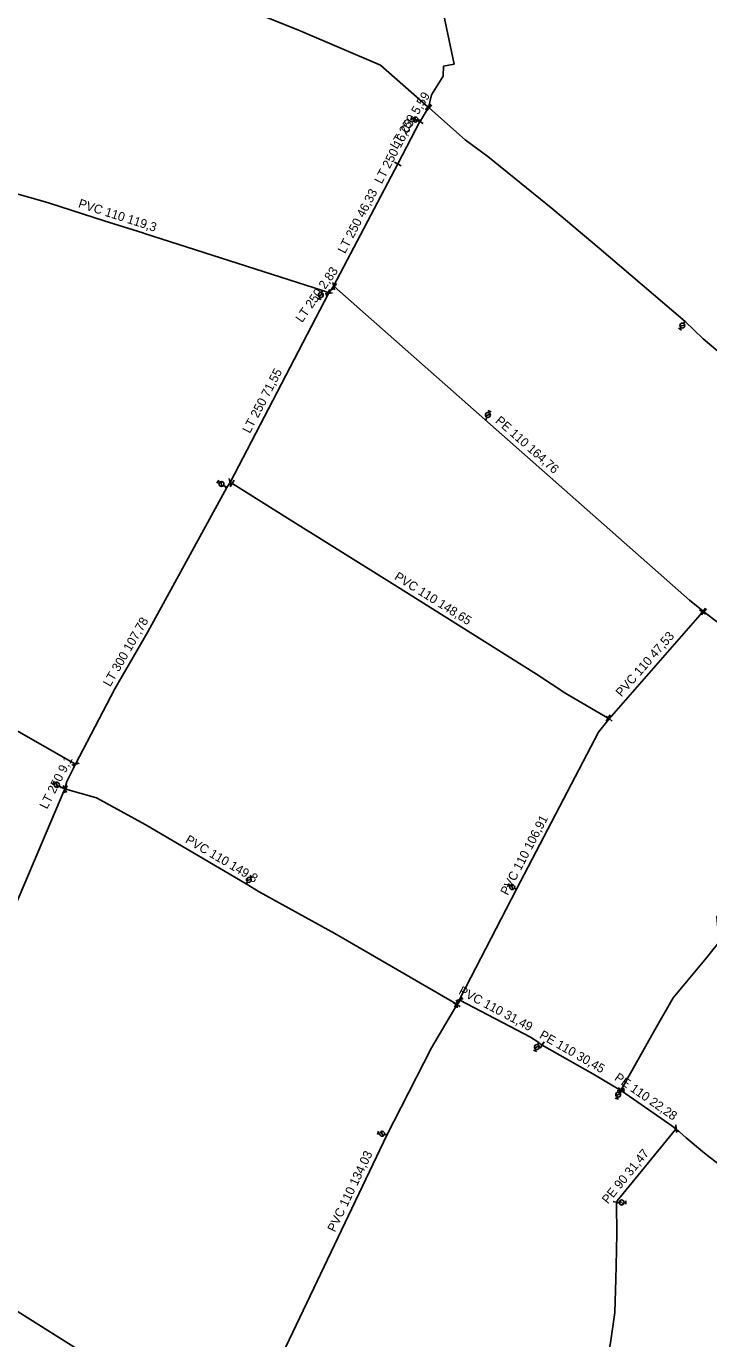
# Model space of a CAD drawing. Extents: x -736619 to -735426, y -1033122 to -1031044.
# Drawn here: x -736078.3 to -735849.4, y -1032731.9 to -1032291.7 of the extents above; entities that cross this region are included whole.
import ezdxf

# ---------------------------------------------------------------- set-up
doc = ezdxf.new("R2010")
doc.units = 0
for name, color, linetype in [('Vrstva 1', 7, 'Continuous'), ('Vrstva 17', 7, 'Continuous'), ('Vrstva 25', 7, 'Continuous'), ('Vrstva 29', 7, 'Continuous'), ('Vrstva 63', 7, 'Continuous')]:
    doc.layers.add(name, color=color, linetype=linetype)

# ---------------------------------------------------------------- blocks, each defined once
blk = doc.blocks.new('100')
at = {"layer": 'Vrstva 1'}
blk.add_circle((0, 0), 0.127, dxfattribs=at)
blk = doc.blocks.new('133')
at = {"layer": 'Vrstva 1'}
for p, q in [((0.28, 0), (0, 0)), ((0.54, 0.58), (1.7, -0.58)), ((1.94, 0), (2.52, 0)), ((2.52, 0.58), (2.52, -0.58))]:
    blk.add_line(p, q, dxfattribs=at)
blk.add_circle((1.105, 0.003), 0.825, dxfattribs=at)
blk = doc.blocks.new('147')
at = {"layer": 'Vrstva 1'}
blk.add_line((0, 1.27), (0, -1.27), dxfattribs=at)

msp = doc.modelspace()

# ---------------------------------------------------------------- linework, layer by layer
at = {"layer": 'Vrstva 17'}
for p, q in [((-735943.596, -1032318.709), (-735943.354, -1032318.926)), ((-735943.354, -1032318.926), (-735943.091, -1032319.148)), ((-735946.267, -1032323.694), (-735953.694, -1032337.895)), ((-735953.694, -1032337.895), (-735975.236, -1032378.911)), ((-735975.236, -1032378.911), (-735976.852, -1032381.236)), ((-735975.007, -1032379.034), (-735975.236, -1032378.911)), ((-735976.852, -1032381.236), (-735977.1, -1032381.05)), ((-736009.96, -1032444.666), (-736009.247, -1032445.08)), ((-735882.778, -1032523.942), (-735851.484, -1032488.165)), ((-735851.484, -1032488.165), (-735851.31, -1032487.854)), ((-735851.007, -1032488.105), (-735851.31, -1032487.854)), ((-735883.116, -1032523.716), (-735882.778, -1032523.942)), ((-736061.756, -1032539.17), (-736061.794, -1032539.148)), ((-736065.083, -1032547.585), (-736065.393, -1032547.472)), ((-735933.82, -1032619.656), (-735934.084, -1032619.516)), ((-735933.82, -1032619.656), (-735933.918, -1032619.842)), ((-735933.038, -1032618.179), (-735933.82, -1032619.656)), ((-735933.038, -1032618.179), (-735932.847, -1032618.28)), ((-735878.86, -1032648.571), (-735878.73, -1032648.384)), ((-735878.635, -1032648.727), (-735878.86, -1032648.571)), ((-735860.343, -1032661.446), (-735878.635, -1032648.727)), ((-735860.514, -1032661.65), (-735860.343, -1032661.446))]:
    msp.add_line(p, q, dxfattribs=at)
for points in [[(-735954.66, -1032212.952), (-735953.407, -1032215.657), (-735948.624, -1032232.346), (-735944.072, -1032253.819), (-735941.595, -1032272.005), (-735934.779, -1032304.372), (-735938.314, -1032305.089), (-735938.478, -1032308.409), (-735942.432, -1032314.719), (-735943.354, -1032318.926)], [(-736058.928, -1032278.254), (-736056.268, -1032278.805), (-736017.452, -1032285.347), (-735998.364, -1032288.387), (-735986.426, -1032293.223), (-735959.541, -1032304.754), (-735943.596, -1032318.709)], [(-735946.267, -1032323.694), (-735946.136, -1032323.443), (-735943.354, -1032318.926)], [(-735815.232, -1032429.97), (-735817.096, -1032425.726), (-735825.831, -1032417.995), (-735851.243, -1032396.548), (-735857.331, -1032390.732), (-735886.184, -1032366.165), (-735901.653, -1032353.103), (-735923.508, -1032335.433), (-735931.065, -1032329.78), (-735943.091, -1032319.148)], [(-736090.814, -1032344.963), (-736090.12, -1032345.24), (-736085.05, -1032346.96), (-736072.79, -1032350.32), (-736070.508, -1032351.05), (-736052.156, -1032356.918), (-736039.257, -1032361.042), (-736038.655, -1032361.234), (-736018.763, -1032367.594), (-735990.126, -1032376.75), (-735978.99, -1032380.31), (-735977.1, -1032381.05)], [(-735851.31, -1032487.854), (-735855.857, -1032484.209), (-735975.007, -1032379.034)], [(-735976.852, -1032381.236), (-735976.884, -1032381.282), (-736009.96, -1032444.666)], [(-736061.756, -1032539.17), (-736048.601, -1032513.958), (-736037.57, -1032494.84), (-736011.041, -1032446.439), (-736009.96, -1032444.666)], [(-736009.247, -1032445.08), (-736009.031, -1032445.206), (-735989.782, -1032457.25), (-735976.766, -1032465.395), (-735954.697, -1032479.204), (-735907.138, -1032508.963), (-735897.368, -1032515.533), (-735883.333, -1032523.592), (-735883.116, -1032523.716)], [(-735774.512, -1032551.19), (-735777.638, -1032548.821), (-735777.852, -1032548.559), (-735778.305, -1032548.082), (-735778.32, -1032548.066), (-735778.583, -1032547.57), (-735808.91, -1032521.893), (-735846.062, -1032491.872), (-735851.007, -1032488.105)], [(-736061.794, -1032539.148), (-736122.796, -1032504.389), (-736141.171, -1032492.334)], [(-735933.038, -1032618.179), (-735932.632, -1032617.411), (-735913.844, -1032581.138), (-735886.355, -1032528.403), (-735882.778, -1032523.942)], [(-736061.756, -1032539.17), (-736064.718, -1032544.986), (-736065.393, -1032547.472)], [(-736065.393, -1032547.472), (-736097.661, -1032623.347), (-736112.001, -1032671.548)], [(-736065.083, -1032547.585), (-736054.76, -1032550.522), (-736038.372, -1032559.446), (-736004.499, -1032579.36), (-736000.228, -1032581.978), (-735974.833, -1032595.991), (-735934.084, -1032619.516)], [(-735878.73, -1032648.384), (-735867.528, -1032628.235), (-735861.393, -1032617.508), (-735850.134, -1032604.11), (-735848.028, -1032601.409), (-735845.899, -1032598.884), (-735846.653, -1032590.394), (-735840.929, -1032583.321), (-735838.698, -1032581.01), (-735832.618, -1032591.43), (-735835.683, -1032596.16), (-735832.7, -1032598.584), (-735824.627, -1032605.661), (-735808.597, -1032618.544), (-735805.533, -1032620.875), (-735802.525, -1032623.525), (-735789.126, -1032634.333), (-735780.475, -1032639.942), (-735778.071, -1032640.132)], [(-735993.808, -1032739.322), (-735993.552, -1032739.478), (-735957.374, -1032663.621), (-735952.591, -1032654.188), (-735942.348, -1032634.305), (-735933.918, -1032619.842)], [(-735932.847, -1032618.28), (-735909.245, -1032630.766), (-735906.405, -1032632.551), (-735906.095, -1032632.901), (-735905.255, -1032633.382)], [(-735905.255, -1032633.382), (-735904.441, -1032633.848), (-735888.312, -1032643.083), (-735878.86, -1032648.571)], [(-735860.514, -1032661.65), (-735880.123, -1032685.632), (-735880.26, -1032686.1)], [(-735792.194, -1032708.488), (-735796.517, -1032710.028), (-735799.727, -1032709.658), (-735805.839, -1032706.136), (-735823.078, -1032691.959), (-735842.414, -1032676.074), (-735849.814, -1032670.401), (-735851.533, -1032669.102), (-735856.931, -1032664.544), (-735860.343, -1032661.446)], [(-735896.6, -1032817.99), (-735895.02, -1032808.86), (-735893.86, -1032801.88), (-735891.68, -1032789.5), (-735890.79, -1032784.47), (-735886.29, -1032757.99), (-735885.01, -1032749.55), (-735882.73, -1032735.25), (-735882.27, -1032732.42), (-735880.96, -1032723.07), (-735880.62, -1032711.86), (-735880.51, -1032707.38), (-735880.24, -1032696.67), (-735880.35, -1032686.61), (-735880.26, -1032686.1)], [(-736053.341, -1032740.177), (-736060.689, -1032735.583), (-736061.081, -1032735.355), (-736087.044, -1032719.018), (-736087.511, -1032718.722), (-736112.832, -1032702.648), (-736113.092, -1032702.546), (-736117.604, -1032699.702)]]:
    msp.add_lwpolyline(points, dxfattribs=at)
at = {"layer": 'Vrstva 63'}
for p, q in [((-735978.99, -1032380.31), (-735979.141, -1032380.783)), ((-736011.041, -1032446.439), (-736011.933, -1032445.847))]:
    msp.add_line(p, q, dxfattribs=at)
for points in [[(-735946.136, -1032323.443), (-735946.367, -1032323.322), (-735946.68, -1032323.258)], [(-735857.331, -1032390.732), (-735857.543, -1032390.982), (-735857.669, -1032391.173)], [(-735924.345, -1032423.754), (-735924.016, -1032423.382), (-735923.9, -1032423.109)], [(-736065.393, -1032547.472), (-736066.706, -1032546.888), (-736067.063, -1032546.687)], [(-736004.499, -1032579.36), (-736004.375, -1032579.131), (-736004.243, -1032578.93)], [(-735913.844, -1032581.138), (-735914.089, -1032581.045), (-735914.332, -1032580.93)], [(-735906.405, -1032632.551), (-735906.536, -1032632.776), (-735906.632, -1032633.017)], [(-735879.181, -1032648.385), (-735879.373, -1032648.715), (-735879.451, -1032648.974)], [(-735957.374, -1032663.621), (-735957.604, -1032663.499), (-735957.884, -1032663.422)], [(-735880.26, -1032686.1), (-735880.02, -1032686.17), (-735879.726, -1032686.17)]]:
    msp.add_lwpolyline(points, dxfattribs=at)

# ---------------------------------------------------------------- block references
at = {"layer": 'Vrstva 25'}
for p, xscale, yscale, rotation in [((-735946.68, -1032323.258), 1.0045862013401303, 1.00458620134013, 166.82590933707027), ((-735979.141, -1032380.783), 0.9999999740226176, 0.9999999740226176, -108.99999960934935), ((-735857.669, -1032391.173), 0.9999999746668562, 0.999999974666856, -124.00000045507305), ((-735923.9, -1032423.109), 0.9999999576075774, 0.9999999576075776, 66.99999911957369), ((-736011.933, -1032445.847), 0.9999999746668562, 0.999999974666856, 145.99999954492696), ((-736067.063, -1032546.687), 1.0037041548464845, 1.0037041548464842, 150.62079141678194), ((-736004.243, -1032578.93), 0.9999999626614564, 0.9999999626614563, 57.00000159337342), ((-735914.332, -1032580.93), 1.0169561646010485, 1.0169561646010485, 153.0239835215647), ((-735906.632, -1032633.017), 0.9999999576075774, 0.9999999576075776, -113.00000088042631), ((-735879.451, -1032648.974), 0.9999999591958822, 0.9999999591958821, -107.99999945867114), ((-735957.884, -1032663.422), 0.999999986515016, 0.9999999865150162, 164.99999987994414)]:
    msp.add_blockref('133', p, dxfattribs=dict(at, xscale=xscale, yscale=yscale, rotation=rotation))
msp.add_blockref('133', (-735879.726, -1032686.17), dxfattribs=at)
at = {"layer": 'Vrstva 29'}
for p, xscale, yscale, rotation in [((-735943.596, -1032318.709), 0.9999999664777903, 0.9999999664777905, -42.999998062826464), ((-735943.354, -1032318.926), 0.9999999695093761, 0.9999999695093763, 138.9999986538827), ((-735943.091, -1032319.148), 0.9999999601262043, 0.9999999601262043, -41.999998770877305), ((-735946.267, -1032323.694), 0.999999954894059, 0.9999999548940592, -119.00000058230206), ((-735953.694, -1032337.895), 0.999999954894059, 0.9999999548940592, -119.00000058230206), ((-735975.007, -1032379.034), 0.9999999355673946, 0.9999999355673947, 145.00000060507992), ((-735975.236, -1032378.911), 1.0045862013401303, 1.00458620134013, -166.82590933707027), ((-735976.852, -1032381.236), 0.9999999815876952, 0.9999999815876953, -82.0000004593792), ((-735977.1, -1032381.05), 1.0037041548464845, 1.0037041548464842, 150.62079141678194), ((-736009.96, -1032444.666), 1.0009847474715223, 1.0009847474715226, 14.22432628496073), ((-736009.247, -1032445.08), 0.9999999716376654, 0.9999999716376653, 150.00000103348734), ((-735851.484, -1032488.165), 0.9999999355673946, 0.9999999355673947, 55.0000006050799), ((-735851.31, -1032487.854), 0.9999999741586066, 0.9999999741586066, -39.999998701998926), ((-735851.007, -1032488.105), 0.9999999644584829, 0.999999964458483, -39.000001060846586), ((-735883.116, -1032523.716), 0.9999999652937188, 0.9999999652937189, 148.0000026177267), ((-735882.778, -1032523.942), 0.9999999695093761, 0.9999999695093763, -131.00000134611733), ((-736061.756, -1032539.17), 0.9999999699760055, 0.9999999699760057, 106.99999966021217), ((-736061.794, -1032539.148), 0.9999999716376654, 0.9999999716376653, 150.00000103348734), ((-736065.393, -1032547.472), 1.025136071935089, 1.0251360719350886, -154.74924162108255), ((-736065.083, -1032547.585), 1.0335064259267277, 1.033506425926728, 156.95871849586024), ((-735933.918, -1032619.842), 0.999999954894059, 0.9999999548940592, 60.999999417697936), ((-735934.084, -1032619.516), 1.0037041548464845, 1.0037041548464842, 150.62079141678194), ((-735933.038, -1032618.179), 0.9999999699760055, 0.9999999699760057, 106.99999966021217), ((-735932.847, -1032618.28), 1.0072562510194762, 1.0072562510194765, 151.23333635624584), ((-735905.255, -1032633.382), 0.9999999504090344, 0.9999999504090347, -31.000001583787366), ((-735878.73, -1032648.384), 0.9999999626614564, 0.9999999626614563, -122.99999840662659), ((-735878.635, -1032648.727), 0.9999999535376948, 0.9999999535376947, -36.000001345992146), ((-735878.86, -1032648.571), 0.9999999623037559, 0.999999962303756, -80.99999986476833), ((-735860.514, -1032661.65), 0.9999999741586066, 0.9999999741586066, 50.000001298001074), ((-735860.343, -1032661.446), 0.9999999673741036, 0.9999999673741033, 3.999999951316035), ((-735880.26, -1032686.1), 0.9999999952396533, 0.9999999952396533, 77.00000056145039)]:
    msp.add_blockref('147', p, dxfattribs=dict(at, xscale=xscale, yscale=yscale, rotation=rotation))
msp.add_blockref('147', (-735933.82, -1032619.656), dxfattribs=at)
at = {"layer": 'Vrstva 63'}
for p, xscale, yscale, rotation in [((-735946.367, -1032323.322), 1.0275072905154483, 1.027507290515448, -24.689105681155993), ((-735979.066, -1032380.548), 0.9999999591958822, 0.9999999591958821, 72.00000054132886), ((-735857.543, -1032390.982), 0.9999999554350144, 0.9999999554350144, 53.00000079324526), ((-735924.016, -1032423.382), 0.9999999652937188, 0.9999999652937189, 58.00000261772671), ((-736011.487, -1032446.143), 0.9999999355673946, 0.9999999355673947, -34.99999939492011), ((-736066.706, -1032546.888), 0.9999999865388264, 0.9999999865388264, -30.00000044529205), ((-736004.375, -1032579.131), 0.9999999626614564, 0.9999999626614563, 57.00000159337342), ((-735914.089, -1032581.045), 1.0138864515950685, 1.0138864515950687, -27.5653151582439), ((-735906.536, -1032632.777), 0.9999999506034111, 0.9999999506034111, 67.99999971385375), ((-735879.373, -1032648.715), 0.9999999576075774, 0.9999999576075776, 66.99999911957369), ((-735957.604, -1032663.499), 1.022584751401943, 1.022584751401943, -25.818974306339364), ((-735880.02, -1032686.17), 1.00837761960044, 1.00837761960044, -11.626378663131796)]:
    msp.add_blockref('100', p, dxfattribs=dict(at, xscale=xscale, yscale=yscale, rotation=rotation))

# ---------------------------------------------------------------- texts
for s, height, rotation, p in [('LT 250 5,59', 2.99999, 58.37, (-735953.998, -1032333.157)), ('LT 250 16,03', 2.99999, 62.39, (-735959.106, -1032344.792)), ('LT 250 46,33', 2.99999, 62.29, (-735971.4, -1032368.166)), ('PVC 110 119,3', 2.99999, 342.27, (-736061.075, -1032352.386)), ('LT 250 2,83', 2.99999, 55.2, (-735985.8, -1032391.307)), ('LT 250 71,55', 2.99999, 62.44, (-736003.306, -1032428.456)), ('PE 110 164,76', 2.99999, 318.56, (-735921.21, -1032424.384)), ('PVC 110 148,65', 2.99999, 327.96, (-735955.11, -1032477.055)), ('LT 300 107,78', 2.99999, 60.02, (-736050.147, -1032513.425)), ('PVC 110 47,53', 2.99999, 48.82, (-735878.672, -1032516.816)), ('LT 250 9,1', 3, 63.01, (-736071.345, -1032554.473)), ('PVC 110 106,91', 2.99999, 62.47, (-735916.819, -1032583.386)), ('PVC 110 149,8', 2.99999, 329.55, (-736025.224, -1032565.319)), ('PVC 110 31,49', 2.99999, 332.12, (-735933.532, -1032616.106)), ('PE 110 30,45', 2.99999, 330.21, (-735906.462, -1032630.848)), ('PE 110 22,28', 2.99999, 325.19, (-735881.3, -1032644.925)), ('PVC 110 134,03', 2.99999, 64.5, (-735974.751, -1032696.338)), ('PE 90 31,47', 2.99999, 50.73, (-735883.214, -1032686.885))]:
    msp.add_text(s, height=height, rotation=rotation, dxfattribs=at).set_placement(p)

doc.saveas('drawing.dxf')
